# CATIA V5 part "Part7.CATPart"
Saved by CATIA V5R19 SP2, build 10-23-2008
Part number: Part7
Bounding box of the stored display mesh (mm): x -1095.175 to 1915.919, y -796.851 to 796.851, z 246.836 to 1004.487
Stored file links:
  C:\BEHROOZ\catia learning\tarh haye mashin\hb\Part7.CATPart
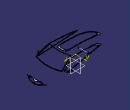
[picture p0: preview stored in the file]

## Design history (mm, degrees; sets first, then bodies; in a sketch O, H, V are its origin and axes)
Body1 (main body)
  Set1
    DatumSurface1
    ThickSurface1: Surface DatumSurface1, TopOffset 1, BotOffset 1
    DatumSurface2 to DatumSurface4
    Plane1: stored without definition
    Sketch1 on Plane1, origin (0, 750, 0), H (-1, 0, 0), V (0, 0, 1)
      unspec C1
      unspec C2
      unspec C3
      unspec C4
      unspec C5
      arc A1 centre (190365.2493, 392918.3255) radius 435646.4005 from (380.1217, 880.7793) to (501.3259, 822.0657) ccw
      unspec C6
      unspec C7
      unspec C8
      line L1 (-1024.8206, 631.2352) -> (-1091.9393, 669.0892)
      unspec C9
      line L2 (-1093.6186, 694.278) -> (-1093.0574, 694.6951)
  DatumSurface5
  ThickSurface2: Surface DatumSurface5, TopOffset 8, BotOffset 1
  DatumSurface6
  ThickSurface3: Surface DatumSurface6, TopOffset 8, BotOffset 1
  DatumSurface7
  ThickSurface4: Surface DatumSurface7, TopOffset 8, BotOffset 1
  Plane2: stored without definition
  Pocket1: profile Sketch1, direction (0, -1, 0), length 20, opposite side length -2022
  Sketch2 on Plane2, origin (1983, 0, 0), H (0, 1, 0), V (0, 0, 1)
    unspec C1
    unspec C2
    unspec C3
    unspec C4
    unspec C5
    unspec C6
    unspec C7
    unspec C8
  Pocket2: profile Sketch2, direction (-1, 0, 0), length 1331
  DatumSurface8
  ThickSurface5: Surface DatumSurface8, TopOffset 8, BotOffset 1
  Sketch3 on xy-plane, origin (0, 0, 0), H (1, 0, 0), V (0, 1, 0)
    unspec C1
    unspec C2
    unspec C3
    unspec C4
    unspec C5
    unspec C6
    unspec C7
    unspec C8
    unspec C9
    unspec C10
    unspec C11
    unspec C12
    unspec C13
    unspec C14
    unspec C15
  Pocket3: profile Sketch3, direction (0, 0, 1), length 1331
  Fillet1: radius 6, on edge [face of Pocket1 from Sketch1.A1 | face of ThickSurface2]; edge [face of ThickSurface4 | face of Pocket1 from Sketch1.L1]
  Fillet2: radius 3, on edge [face of ThickSurface3 | face of Pocket2 from Sketch2.C8]
  DatumSurface9
  Fillet3: radius 7, on edge [face of Pocket3 from Sketch3.C11 | face of ThickSurface5]
  DatumSurface10
  DatumSurface11
  Sketch4 on face of DatumSurface9, origin (619.1394, -809.5627, -201.1706), H (-0.7943, -0.6075, 0), V (0.1176, -0.1538, 0.9811)
  Pad1: profile Sketch4, direction (-0.596, 0.7793, 0.1936), length 1
  DatumSurface12
  Plane3: stored without definition
  Sketch5 on face of DatumSurface11, origin (619.1394, 809.5627, -201.1706), H (-0.7943, 0.6075, 0), V (0.1176, 0.1538, 0.9811)
  Pad2: profile Sketch5, direction (-0.596, -0.7793, 0.1936), length 1
  DatumCurve1
  Plane4: stored without definition
  Sketch6 on Plane3, origin (0, 750, 0), H (-1, 0, 0), V (0, 0, 1)
    projected arc E1 centre (-4224.9857, 1613.9741) radius 4330.792 from (-6.9407, 632.2123) to (14.261, 728.2274) ccw from edge of DatumCurve1
    projected arc E2 centre (-4224.9857, 1613.9741) radius 4330.792 from (-6.9407, 632.2123) to (53.1995, 941.0022) ccw from edge of DatumCurve1
  Pocket4: profile Sketch6, direction (0, -1, 0), length 3384, thin wall 1
  DatumCurve2
  Plane5: stored without definition
  Sketch7 on Plane4, origin (0, 0, 449), H (1, 0, 0), V (0, 1, 0)
    line L1 (-348.926, 200.8131) -> (-348.926, -207.6026)
  Pocket5: profile Sketch7, direction (0, 0, -1), length 3384, opposite side length 619, thin wall 2
  Sketch8 on Plane5, origin (0, 0, 449), H (1, 0, 0), V (0, 1, 0)
    projected line E1 (-348.926, -201.5808) -> (-348.926, -188.1575) from edge [face of Pocket5 | face of ThickSurface5]
    projected line E2 (-348.926, -201.5808) -> (-348.926, 208.1953) from edge [face of Pocket5 | face of ThickSurface5]
  DatumSurface13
